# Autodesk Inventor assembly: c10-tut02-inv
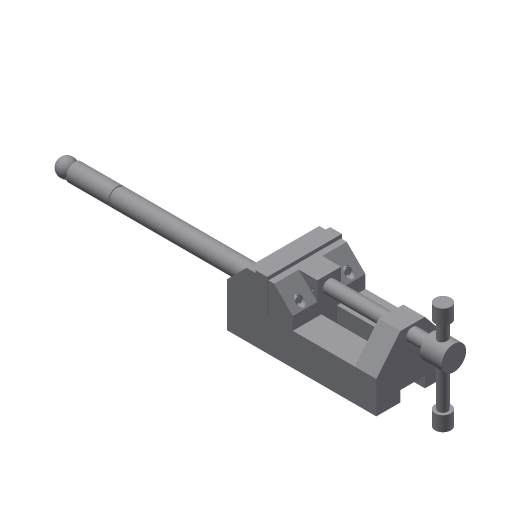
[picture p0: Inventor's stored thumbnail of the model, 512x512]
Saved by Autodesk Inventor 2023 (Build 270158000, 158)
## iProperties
Created: 2009-05
Part Number: c10-tut02-inv
Document SubType Name: Assembly
Designer: Sham
Author: Sham
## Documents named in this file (9)
- D:\PROJECTS\Project 2022\Autodesk Inventor For Professional 2023\RESOURCES INVENTOR 2023\RESOURCES INVENTOR 2023\Inventor_2023_tut\Inventor_2023_tut\c10_Inv_2023_tut\c10_Inv_tut_2023\c10_tut02_inv\Drill Press Vice\Drill Press Vice Assembly.iam
- D:\PROJECTS\Project 2022\Autodesk Inventor For Professional 2023\RESOURCES INVENTOR 2023\RESOURCES INVENTOR 2023\Inventor_2023_tut\Inventor_2023_tut\c10_Inv_2023_tut\c10_Inv_tut_2023\c10_tut02_inv\Drill Press Vice\Base.ipt
- D:\PROJECTS\Project 2022\Autodesk Inventor For Professional 2023\RESOURCES INVENTOR 2023\RESOURCES INVENTOR 2023\Inventor_2023_tut\Inventor_2023_tut\c10_Inv_2023_tut\c10_Inv_tut_2023\c10_tut02_inv\Drill Press Vice\Safety Handle.ipt
- D:\PROJECTS\Project 2022\Autodesk Inventor For Professional 2023\RESOURCES INVENTOR 2023\RESOURCES INVENTOR 2023\Inventor_2023_tut\Inventor_2023_tut\c10_Inv_2023_tut\c10_Inv_tut_2023\c10_tut02_inv\Drill Press Vice\Jaw Face.ipt
- D:\PROJECTS\Project 2022\Autodesk Inventor For Professional 2023\RESOURCES INVENTOR 2023\RESOURCES INVENTOR 2023\Inventor_2023_tut\Inventor_2023_tut\c10_Inv_2023_tut\c10_Inv_tut_2023\c10_tut02_inv\Drill Press Vice\Movable Jaw.ipt
- D:\PROJECTS\Project 2022\Autodesk Inventor For Professional 2023\RESOURCES INVENTOR 2023\RESOURCES INVENTOR 2023\Inventor_2023_tut\Inventor_2023_tut\c10_Inv_2023_tut\c10_Inv_tut_2023\c10_tut02_inv\Drill Press Vice\Cap Screw.ipt
- D:\PROJECTS\Project 2022\Autodesk Inventor For Professional 2023\RESOURCES INVENTOR 2023\RESOURCES INVENTOR 2023\Inventor_2023_tut\Inventor_2023_tut\c10_Inv_2023_tut\c10_Inv_tut_2023\c10_tut02_inv\Drill Press Vice\Clamp Screw Handle.ipt
- D:\PROJECTS\Project 2022\Autodesk Inventor For Professional 2023\RESOURCES INVENTOR 2023\RESOURCES INVENTOR 2023\Inventor_2023_tut\Inventor_2023_tut\c10_Inv_2023_tut\c10_Inv_tut_2023\c10_tut02_inv\Drill Press Vice\Clamp Screw.ipt
- D:\PROJECTS\Project 2022\Autodesk Inventor For Professional 2023\RESOURCES INVENTOR 2023\RESOURCES INVENTOR 2023\Inventor_2023_tut\Inventor_2023_tut\c10_Inv_2023_tut\c10_Inv_tut_2023\c10_tut02_inv\Drill Press Vice\Handle Stop.ipt
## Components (11 placed, 8 different names)
1. Base:1 — Mate:1, Flush:1, Insert:1, Insert:2, Insert:3
2. Movable Jaw:1 — Mate:1, Flush:1, Insert:4, Insert:5, Insert:6, Insert:7, Insert:8
3. Safety Handle:1 — Insert:1
4. Jaw Face:1 — Insert:4, Insert:5, Mate:7
5. Jaw Face:2 — Insert:2, Insert:3, Mate:7
6. Cap Screw:1 — Insert:7
7. Cap Screw:2 — Insert:6
8. Clamp Screw:1 — Insert:8, Mate:2
9. Clamp Screw Handle:1 — Mate:2, Insert:9, Insert:10
10. Handle Stop:1 — Insert:10
11. Handle Stop:2 — Insert:9
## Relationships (14: Insert 10, Mate 3, Flush 1)
- Mate:1: Base:1 ↔ Movable Jaw:1
- Flush:1: Base:1 ↔ Movable Jaw:1
- Insert:1: Base:1 ↔ Safety Handle:1
- Insert:2: Base:1 ↔ Jaw Face:2
- Insert:3: Base:1 ↔ Jaw Face:2
- Insert:4: Movable Jaw:1 ↔ Jaw Face:1
- Insert:5: Movable Jaw:1 ↔ Jaw Face:1
- Insert:6: Movable Jaw:1 ↔ Cap Screw:2
- Insert:7: Movable Jaw:1 ↔ Cap Screw:1
- Insert:8: Movable Jaw:1 ↔ Clamp Screw:1
- Mate:2: Clamp Screw:1 ↔ Clamp Screw Handle:1
- Insert:9: Clamp Screw Handle:1 ↔ Handle Stop:2
- Insert:10: Clamp Screw Handle:1 ↔ Handle Stop:1
- Mate:7: Jaw Face:1 ↔ Jaw Face:2
